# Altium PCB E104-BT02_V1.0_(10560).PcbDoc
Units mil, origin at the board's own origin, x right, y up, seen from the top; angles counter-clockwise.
Board outline 2052.36 x 953 mil, 2 copper layers (Top Layer, Bottom Layer); 31 components, 29 nets, 97 pads, 122 vias.
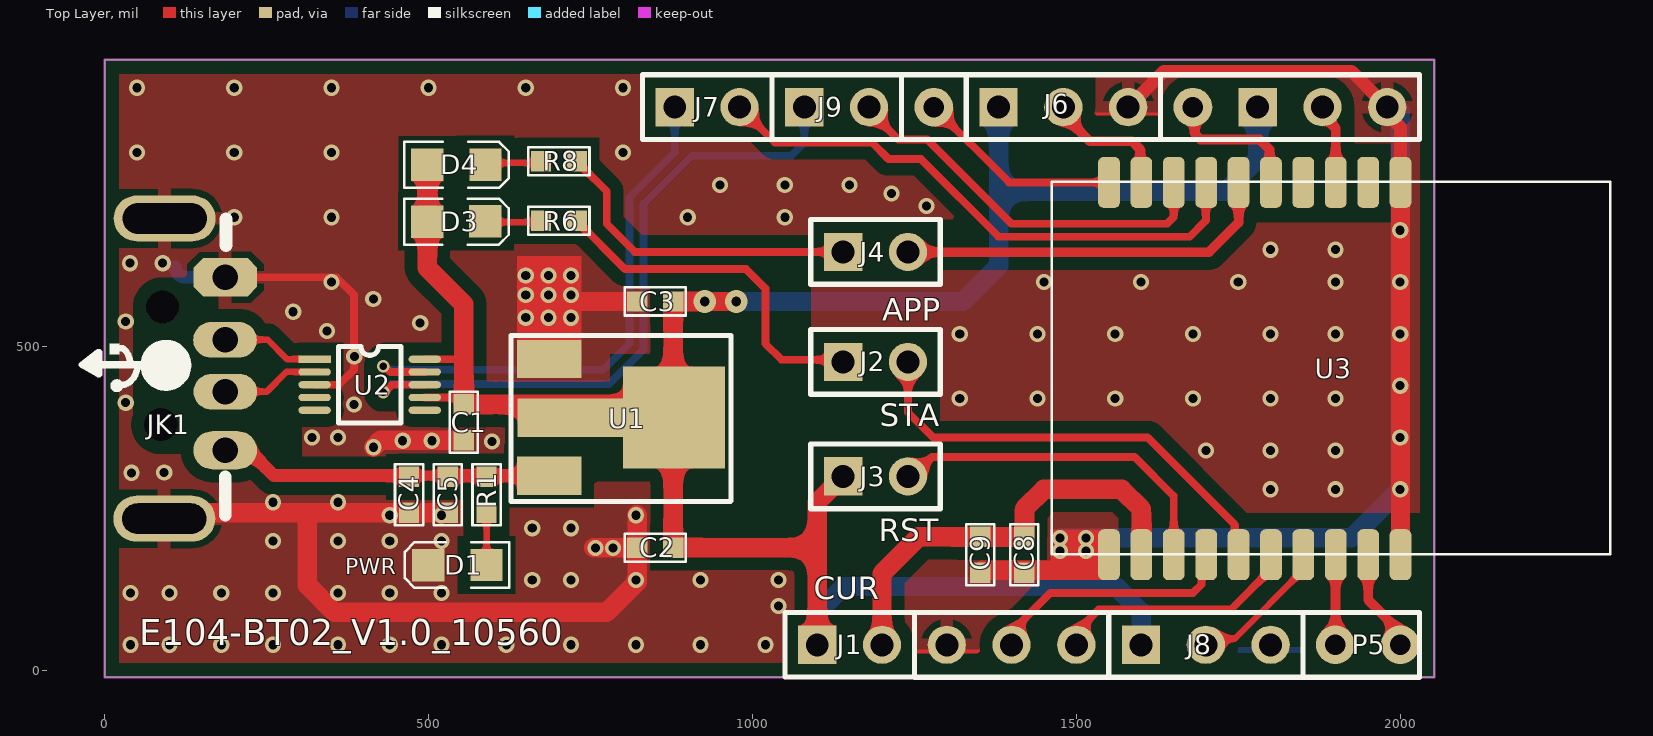
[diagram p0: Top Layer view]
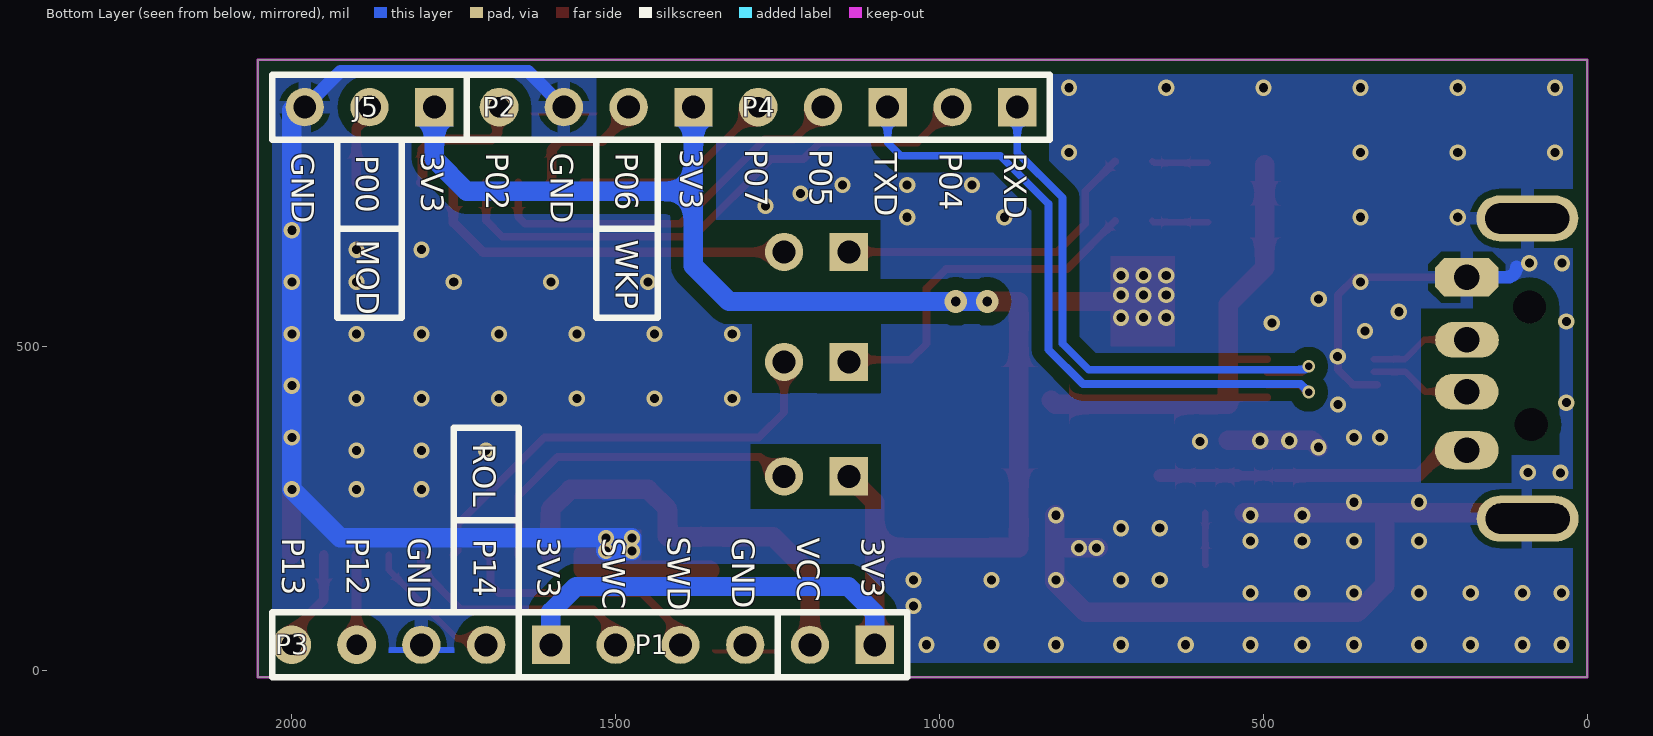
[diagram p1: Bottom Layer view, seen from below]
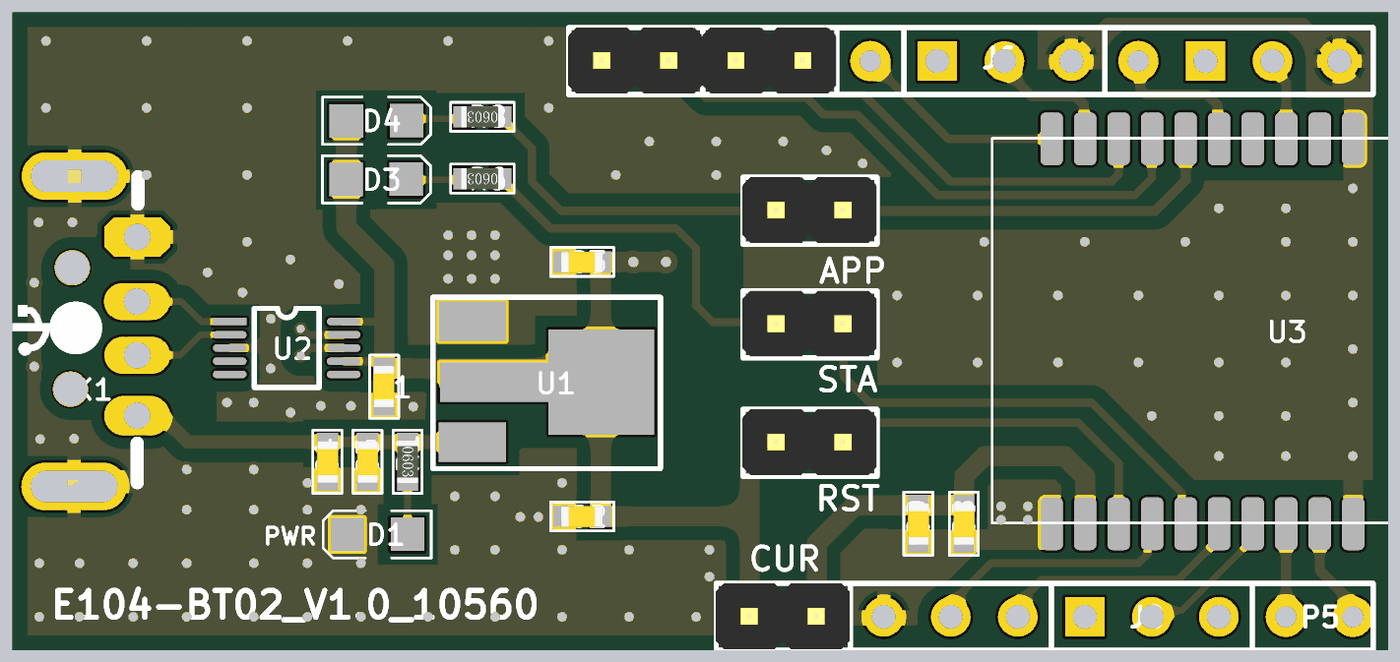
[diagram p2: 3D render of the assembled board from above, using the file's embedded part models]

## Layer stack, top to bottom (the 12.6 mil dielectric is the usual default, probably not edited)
Top Solder: solder mask 0.4, Solder Resist, Dk 3.5
Top Layer: signal copper 1.4
Dielectric1: dielectric 12.6, FR-4, Dk 4.8
Bottom Layer: signal copper 1.4
Bottom Solder: solder mask 0.4, Solder Resist, Dk 3.5

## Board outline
0,-10 2052.36,-10 2052.36,943 0,943

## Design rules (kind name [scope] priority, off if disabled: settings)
Clearance Clearance_1 [InPolygon] p1: gap=20 ignorepadtopadclearanceinfootprint=TRUE
Clearance [All] p2: gap=3 ignorepadtopadclearanceinfootprint=TRUE
ComponentClearance [All] p1 off: gap=10 collisioncheckmode=3 verticalgap=10 showdistances=FALSE
MinimumSolderMaskSliver [All] p1: minsoldermaskwidth=1
PolygonConnect PolygonConnect_4 [All vs IsNamedPolygon('Top Layer-No Net')] p1: thpad.connectstyle=Relief thpad.reliefconductorwidth=20 thpad.reliefentries=4 thpad.polygonreliefangle="90 Angle" thpad.airgapwidth=10 smdpad.connectstyle=Direct smdpad.reliefconductorwidth=10 smdpad.reliefentries=4 smdpad.polygonreliefangle="90 Angle" smdpad.airgapwidth=10 via.connectstyle=Direct via.reliefconductorwidth=10 via.reliefentries=4 via.polygonreliefangle="90 Angle" via.airgapwidth=10
PolygonConnect PolygonConnect_3 [All vs IsNamedPolygon('Top Layer-No Net')] p2: thpad.connectstyle=Relief thpad.reliefconductorwidth=20 thpad.reliefentries=4 thpad.polygonreliefangle="90 Angle" thpad.airgapwidth=10 smdpad.connectstyle=Direct smdpad.reliefconductorwidth=10 smdpad.reliefentries=4 smdpad.polygonreliefangle="90 Angle" smdpad.airgapwidth=10 via.connectstyle=Direct via.reliefconductorwidth=10 via.reliefentries=4 via.polygonreliefangle="90 Angle" via.airgapwidth=10
PolygonConnect PolygonConnect_2 [All vs IsNamedPolygon('Top Layer-No Net')] p3: thpad.connectstyle=Relief thpad.reliefconductorwidth=10 thpad.reliefentries=4 thpad.polygonreliefangle="90 Angle" thpad.airgapwidth=10 smdpad.connectstyle=Direct smdpad.reliefconductorwidth=10 smdpad.reliefentries=4 smdpad.polygonreliefangle="90 Angle" smdpad.airgapwidth=10 via.connectstyle=Direct via.reliefconductorwidth=10 via.reliefentries=4 via.polygonreliefangle="90 Angle" via.airgapwidth=10
PolygonConnect PolygonConnect_1 [All vs IsNamedPolygon('Top Layer-No Net')] p4: thpad.connectstyle=Relief thpad.reliefconductorwidth=10 thpad.reliefentries=4 thpad.polygonreliefangle="90 Angle" thpad.airgapwidth=10 smdpad.connectstyle=Direct smdpad.reliefconductorwidth=10 smdpad.reliefentries=4 smdpad.polygonreliefangle="90 Angle" smdpad.airgapwidth=10 via.connectstyle=Direct via.reliefconductorwidth=10 via.reliefentries=4 via.polygonreliefangle="90 Angle" via.airgapwidth=10
PolygonConnect [All] p5: connectstyle=Direct reliefconductorwidth=10 reliefentries=4 polygonreliefangle="90 Angle" airgapwidth=10
RoutingVias [All] p1: holewidth=28 width=50 viastyle="Through Hole" minholewidth=28 minwidth=50 maxholewidth=28 maxwidth=50
SilkToSilkClearance [All] p1: silktosilkclearance=1
SilkToSolderMaskClearance SilkscreenOverComponentPads [IsPad] p1: minsilkscreentomaskgap=1 clearancetoexposedcopper=TRUE
SolderMaskExpansion [All] p1: expansion=4 istentingtop=FALSE
Width [All] p1: maxlimit=50 minlimit=10 preferedwidth=10
26 further rules are at their usual default settings.

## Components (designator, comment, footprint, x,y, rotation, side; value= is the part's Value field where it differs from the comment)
C1 "Cap" E-CAP-0603 554.54,383.52 r90 top value=100nF
C2 "10uF" E-CAP-0603 850,190 r180 top
C3 "0u1F" E-CAP-0603 850,570 r180 top
C4 "10uF" E-CAP-0603 469.83,271.6 r270 top
C5 "0u1F" E-CAP-0603 529.66,271.6 r270 top
C8 "0.1uF" E-CAP-0603 1419.48,179 r270 top value=0.01uF
C9 "1uF" E-CAP-0603 1351.48,179 r270 top value=0.01uF
D1 "LED_RED" LED0805 544.48,163 r180 top
D3 "LED_GREEN" LED0805 542.67,693.49 r0 top
D4 "LED_RED" LED0805 542.96,781.01 r0 top
J1 "CUR" E-2P-2.54-1 1100,40 r0 top
J2 "J_STATE" E-2P-2.54-1 1140,476.74 r0 top
J3 "J_RESET" E-2P-2.54-1 1140,300 r0 top
J4 "J_APP" E-2P-2.54-1 1140,646.55 r0 top
J5 "J_MOD" E-3P-2.54-1 1880,870 r0 bottom
J6 "J_WK" E-3P-2.54-1 1480,870 r0 top
J7 "J_TX" E-2P-2.54-1 880,870 r0 top
J8 "J_ROLE" HDR1X3 1600,40 r0 top
J9 "J_RX" E-2P-2.54-1 1080,870 r0 top
JK1 "USB-A" USB-AG-DIP 136.36,466.4 r0 top
P1 "DBG" E-4P-2.54-1 1450,40 r180 bottom
P2 "P02" E-1×1P-1 1680,870 r180 bottom
P3 "P13" E-1×1P-1 2000,40 r0 bottom
P4 "P07" E-1×1P-1 1280,870 r0 bottom
P5 "P12" E-1×1P-1 1900,40 r0 top
R1 "1K" E-RES-0603 589.48,271.6 r270 top
R6 "1K" E-RES-0603 701.15,694.45 r180 top value=4K7
R8 "1K" E-RES-0603 701.15,786.74 r180 top value=4K7
U1 "AMS1117-3.3" SOT-223 782.36,391.13 r270 top
U2 "CH340X" MSOP10 324.13,480.86 r270 top
U3 "E104-BT02_V1.1" E104-BT02_V1.1 1775.48,466.4 r270 top locked

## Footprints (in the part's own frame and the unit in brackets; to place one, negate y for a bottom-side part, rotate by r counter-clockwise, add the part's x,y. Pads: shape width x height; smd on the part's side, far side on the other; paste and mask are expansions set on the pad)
E104-BT02_V1.1 [mm]
  rrect50% 2x0.85 smd: 1(-7.3,5.715) 2(-7.3,4.445) 3(-7.3,3.175) 4(-7.3,1.905) 5(-7.3,0.635) 6(-7.3,-0.635) 7(-7.3,-1.905) 8(-7.3,-3.175) 9(-7.3,-4.445) 10(-7.3,-5.715) 11(7.3,-5.715) 12(7.3,-4.445) 13(7.3,-3.175) 14(7.3,-1.905) 15(7.3,-0.635) 16(7.3,0.635) 17(7.3,1.905) 18(7.3,3.175) 19(7.3,4.445) 20(7.3,5.715)
  silkscreen extent -7.33,-7.96 7.27,13.94
E-1×1P-1 [mm]
  round 1.52 hole 0.8: 1(0,0)
E-2P-2.54-1 [mm] "Connector; Header;2pins"
  rect 1.5x1.5 hole 0.9: 1(0,0)
  round 1.5 hole 0.9: 2(2.54,0)
  silkscreen extent -1.27,-1.27 3.81,1.27, body extent -1.29,-1.22 3.79,1.27, height 8.54
E-3P-2.54-1 [mm] "Connector; Header; 3 pins"
  rect 1.5x1.5 hole 0.9: 1(-2.54,0)
  round 1.5 hole 0.9: 2(0,0) 3(2.54,0)
  silkscreen extent -3.81,-1.27 3.81,1.27
E-4P-2.54-1 [mm] "Connector; Header; 4pins"
  rect 1.5x1.5 hole 0.9: 1(-3.81,0)
  round 1.5 hole 0.9: 2(-1.27,0) 3(1.27,0) 4(3.81,0)
  silkscreen extent -5.08,-1.27 5.08,1.27
E-CAP-0603 [mm]
  rect 0.8x0.8 smd: 1(-0.7,0) 2(0.7,0)
  silkscreen extent -1.2,-0.55 1.2,0.55, body extent -0.79,-0.39 0.81,0.41, height 0.92
E-RES-0603 [mm]
  rect 0.8x0.8 smd: 1(-0.7,0) 2(0.7,0)
  silkscreen extent -1.2,-0.55 1.2,0.55, body extent -0.8,-0.4 0.8,0.4, height 0.45
HDR1X3 [mm] "Connector; Header; 3 Position"
  rect 1.5x1.5 hole 0.9: 1(0,0)
  round 1.5 hole 0.9: 2(2.54,0) 3(5.08,0)
  silkscreen extent -1.27,-1.27 6.35,1.27
LED0805 [mil]
  rect 50x50 smd: A(-44.9,-0.18) K(44.9,0.18)
  silkscreen extent -80,-36 81,35
MSOP10 [mil]
  rect 11x50 smd: 1(0,0)
  oval 11x50 smd: 2(19.68,0) 3(39.37,0) 4(59.06,0) 5(78.74,0) 6(78.74,170) 7(59.06,170) 8(39.37,170) 9(19.68,170) 10(0,170)
  silkscreen extent -20,37 98,133
SOT-223 [mm]
  rect 1.5x2.54 smd: 1(-2.29,-2.444) 3(2.29,-2.444)
  rect 4x4 smd: 2(0.013,2.444)
  rect 1.5x5.04 smd: 2(0.013,-1.156)
  silkscreen extent -3.21,-3.93 3.3,4.69
USB-AG-DIP [mm]
  oval 2.5x1.5 hole 1: 1(1.26,-3.202)
  oval 2.5x1.4 hole 1: 2(1.266,-0.909) 3(1.254,1.129)
  oct 2.5x1.5 hole 1: 4(1.266,3.581)
  oval 4x1.8 hole 1.2 slot 3.3 at 0 deg: 5(-1.127,-5.886) 6(-1.113,5.886)
  round 1.27 hole 1.3: 7(-1.198,2.41) 8(-1.266,-2.194)
  silkscreen extent -4.36,-5.74 1.29,5.87

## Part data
C1: "Capacitor"
C2 C3 C4 C5: library part cap0603, "0603"
C8 C9: library part Cap, "0603"
D1 D3 D4: library part LED, "0805"
J1 J2 J3 J4 J7 J9: library part JMP2, "HDR1X2"
J5 J6 J8: library part JMP3, "HDR1X3"
JK1: "USB-AG-DIP"
P1: library part "Header 4H", "HDR1X4"
P2 P3 P4 P5: library part "Header 1H", "HDR1X1"
R1: library part res0603, "0603"
R6 R8: library part Res2, "0603"
U1: "SOT-223"
U2: "USB to TTL Serial / UART"
U3: library part E104-BT02

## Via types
v1: diameter 25, hole 14, Top Layer to Bottom Layer, tented both sides, 118 vias
v2: diameter 20, hole 12, Top Layer to Bottom Layer, tented both sides, 2 vias
v3: diameter 35, hole 15, Top Layer to Bottom Layer, tented both sides, 2 vias

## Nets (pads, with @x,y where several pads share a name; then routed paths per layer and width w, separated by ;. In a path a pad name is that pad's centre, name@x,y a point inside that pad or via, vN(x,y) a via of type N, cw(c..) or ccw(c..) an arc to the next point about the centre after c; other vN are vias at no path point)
APP: J4.1 R8.1 | length 498.7
  Top Layer w12: R8.1@728.71,786.32 729.13,786.32 738.46,776.99 738.46,776.57 775,740.03 775,690 818.45,646.55 J4.1
DN: JK1.2 U2.2 | length 122.1
  Top Layer w10: JK1.2@220.48,431 250.48,431 280.79,461.31 U2.2@330,461.31
DP: JK1.3 U2.1 | length 123.9
  Top Layer w10: JK1.3@218.48,511 251.48,511 281.48,481 U2.1@330,481
GND: C1.1 C2.2 C3.2 C4.2 C5.2 C8.2 C9.2 D1.K J5.3 J6.3 J8.3 JK1.4 JK1.5 JK1.6 P1.4 U1.1 U2.3 U3.1 U3.11 U3.20 | length 5028.7
  Top Layer w12: JK1.4 357.62,607.38 385,580 385,465 361.49,441.49 U2.3
  Top Layer w20: J6.3 1635,925 1925,925 J5.3 1980,859.43 2000.48,838.95 2000.48,764.52 U3.1
  Top Layer w30: JK1.5 146.35,234.65 155.73,244.04 312.78,244.04 ; v1(415,345) 425.96,355.96 C1.1 ; C5.2 C4.2 312.78,244.04 ; 705,565 710,570 C3.2 ; v1@755,190 C2.2 ; v1(820,140) 820,135.46 774.54,90 355,90 312.78,132.22 312.78,244.04 ; v1@821.63,240.78 822.44,239.97 C2.2 ; v1@822.44,137.56 C2.2 ; C9.2@1355,155 1548.75,155 1550.48,156.73 U3.11 ; U3.1@2000,765 U3.1@2000.48,764.52 ; U3.20 U3.1
  Bottom Layer w20: 109,623 ccw(c124.62,623) 124.62,607.38 JK1.4 ; J6.3 1635,925 1925,925 J5.3
  Bottom Layer w30: v1(1515,185) v1(1475,185) v1(1475,205) v1(1515,205) 1925,205 v1(2000,280) v1(2000,360) v1(2000,440) v1(2000,520) v1(2000,600) v1(2000,680) J5.3@2000,865
  other v1: 40,40 100,40 180,40 260,40 360,40 440,40 520,40 620,40 720,40 820,40 920,40 1020,40 1040,100 40,120 100,120 180,120 260,120 360,120 440,120 520,120 660,140 720,140 920,140 1040,140 757.65,189.2 784.54,189.2 260,200 360,200 440,200 520,200 660,220 720,220 440,240 520,240 820,240 260,260 360,260 1800,280 1900,280 41.22,305.49 91.83,306.07 1700,340 1800,340 1900,340 598,354 460,355 505,355 320,360 360,360 385.06,410.83 32.4,413.76 1320,420 1440,420 1560,420 1680,420 1800,420 1900,420 385.35,485.2 1320,520 1440,520 1560,520 1680,520 1800,520 1900,520 343.22,524.24 487.02,537 32.4,539.09 650,545 685,545 720,545 290.95,554.11 414.7,573.7 650,580 685,580 720,580 350,600 1450,600 1600,600 1750,600 1900,600 650,610 685,610 720,610 38.87,629.12 89.47,629.12 1800,650 1900,650 200,700 350,700 900,700 1050,700 1268.51,717.26 1214.54,736.69 950,750 1050,750 1150,750 50,800 200,800 350,800 800,800 50,900 200,900 350,900 500,900 650,900 800,900
NC_VPP: U3.2
NetD1_A: D1.A R1.2 | length 80.9
  Top Layer w10: D1.A 589.48,163.28 R1.2
NetD3_K: D3.K R6.2 | length 87.3
  Top Layer w10: D3.K@585.05,692.63 669.8,692.63 R6.2@671.62,694.45
NetD4_K: D4.K R8.2 | length 86.6
  Top Layer w10: D4.K@586.15,783.92 668.8,783.92 R8.2@671.62,786.74
P00: J5.2 U3.3 | length 124.7
  Top Layer w15: J5.2 1880,858.08 1900.48,837.6 U3.3
P01: U3.4
P02: P2.1 U3.5 | length 219.5
  Top Layer w15: P2.1 1682.95,867.05 1682.95,828.81 1691.73,820.03 1782.86,820.03 1798.27,804.61 1798.27,756.01 U3.5
P03: J4.2 U3.6 | length 591.7
  Top Layer w15: J4.2 1240.35,646.2 1705,646.2 1750.58,691.78 1750.58,753.7 U3.6
P04: J7.2 U3.7 | length 872.2
  Top Layer w12: J7.2 1035,815 1185,815 1210,790 1260,790 1380,670 1675,670 1700,695 1700,753.32 U3.7
P05: J9.2 U3.8 | length 605.6
  Top Layer w12: J9.2 1180,865 1225,820 1270,820 1400,690 1640,690 1650.48,700.48 U3.8
P06: J6.2 U3.9 | length 204.5
  Top Layer w15: J6.2 1480,858.14 1520.6,817.55 1586.15,817.55 1598.68,805.02 1598.68,755.61 U3.9
P07: P4.1 U3.10 | length 318.6
  Top Layer w12: P4.1 1396.2,753.8 U3.10
P11: J2.2 U3.15 | length 703
  Top Layer w12: J2.2 1240,399.07 1279.07,360 1610,360 1744.41,225.59 1744.41,185.07 U3.15
P12: P5.1 U3.18 | length 139.2
  Top Layer w15: P5.1 1900.24,40.24 1900.24,178.76 U3.18
P13: P3.1 U3.19 | length 139.5
  Top Layer w15: U3.19 1950.48,109.52 P3.1@2000,60
P14: J8.2 U3.17 | length 221.8
  Top Layer w10: J8.2 1709.39,49.39 1744.39,49.39 1850.48,155.48 U3.17
RESET_H: J3.2 U3.13 | length 538.5
  Top Layer w12: J3.2 1247.21,300 1277.21,330 1590,330 1650.48,269.52 U3.13
STATE: J2.1 R6.1 | length 551.3
  Top Layer w12: R6.1 803.16,620 990,620 1020,590 1020,505 1045,480 1136.74,480 J2.1
SWC: P1.2 U3.16 | length 363
  Top Layer w12: P1.2@1500,60 1535,95 1739.12,95 1800.48,156.36 U3.16
SWD: P1.3 U3.14 | length 372.3
  Top Layer w12: P1.3@1400,60 1460,120 1680,120 1693.41,133.41 1693.41,171.93 U3.14
TTL_RXD: J7.1 U2.9 | length 860.8
  Top Layer w12: v2(430,470) 432.16,470 440.99,461.17 U2.9
  Bottom Layer w12: v2(430,470) 435.5,464.5 769.5,464.5 810,505 810,730 880,800 J7.1
TTL_TXD: J9.1 U2.8 | length 1065.2
  Top Layer w12: v2(430,430) 432.16,430 443.65,441.49 U2.8
  Bottom Layer w12: v2(430,430) 442.5,442.5 778.61,442.5 832,495.89 832,720.89 906.11,795 1060,795 1080,815 J9.1
V3.3: C1.2 C2.1 C3.1 D3.A D4.A J1.1 J3.1 J5.1 J6.1 J8.1 P1.1 U1.2 U2.7 U2.10 | length 3568.6
  Top Layer w12: U2.7 543.81,421.8 C1.2 ; U2.10 547.12,480.86 554.54,488.27
  Top Layer w30: D4.A 498.06,621.94 554.54,565.46 554.54,488.27 C1.2 821.25,411.08 U1.2@827.37,417.19 ; v3(975,570) v3(926.28,570) C3.1 C2.1 1100,190 ; J1.1@1100,60 1100,190 ; J3.1 1100,260 1100,190
  Bottom Layer w30: v3(926.28,570) v3(975,570) 1325,570 1380,625 1380,740 ; J1.1@1100,60 1100,89 1141,130 1561,130 1600,91 J8.1@1600,60 ; J6.1 1380,740 ; J5.1 1780,790 1730,740 1380,740
VBUS: C4.1 C5.1 JK1.1 R1.1 U1.3 | length 609.4
  Top Layer w15: C4.1@480.01,301.13 539.83,301.13 599.66,301.13 U1.3@659.48,301.13
  Top Layer w20: JK1.1 222.27,340.34 261.48,301.13 C4.1@480.01,301.13 ; C5.1@539.83,301.13 599.66,301.13 U1.3@659.48,301.13
VCC: C8.1 C9.1 J1.2 U3.12 | length 652.6
  Top Layer w30: J1.2@1200,60 1200,150 1256.56,206.56 C9.1 C8.1 1420.23,207.31 1420.23,250.23 1450,280 1570,280 1600.48,249.52 U3.12
pads on no net: JK1.7 JK1.8 U2.4 U2.5 U2.6

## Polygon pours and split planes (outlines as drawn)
GND on Top Layer "Top Layer-No Net" (solid, remove dead copper, pour order 1000): 0,933 2042.36,933 2042.36,0 0,0
GND on Bottom Layer "Top Layer-No Net" (solid, remove dead copper, pour order 1001): 0,933 2042.36,933 2042.36,0 0,0

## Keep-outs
Keep-Out Layer:
  the board outline again, w3.94

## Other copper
Top Layer:
  rectangle net GND: 1459.82,152.95 1549.82,217.95
  rectangle net GND: 636.12,500.51 736.12,640.51
  pour cut-out: 89.18,607.25 ccw(c89.18,561.27) 43.2,561.27 43.2,382.68 cw(c40.53,382.68) 40.53,380.02 ccw(c86.51,380.02) 86.51,334.03 143,334.03 143,606 cw(c144,606) 144,607
  pour cut-out: 474.63,506.86 436.6,506.86 ccw(c436.6,470) 399.74,470 399.74,430 ccw(c430,430) 430,399.74 475,399.74
  region net GND: 1528.8,861.23 1528.8,860.77 ccw(c1532.1,860.77) 1532.1,857.47 1627.04,857.47 ccw(c1627.04,861.23) 1630.8,861.23
  region net GND: 1248.9,31.98 1248.9,31.4 ccw(c1253.05,31.4) 1253.05,27.25 1346.37,27.25 ccw(c1346.37,31.98) 1351.1,31.98
  pour cut-out: -29.86,280.48 81.98,280.48 81.98,189 -25,189
  pour cut-out: 82.54,743.98 82.54,652.33 -11,652.33 -11,744 -14,744
  pour cut-out: 304.63,376.12 304.63,322 221,322 221,429 286,429
  pour cut-out: 637.84,658.7 637.84,667.14 631.94,667.14 631.94,658.62
  pour cut-out: 779.84,291.88 779.84,341.09 756.13,341.09 756.13,292 756,292
  pour cut-out: 830.47,820.47 830.47,924 1017,924 1017,820
  pour cut-out: 1090.47,620.33 1090.47,506.22 1020,506.22 1020,627 1015,627
  pour cut-out: 1289,696.65 1289,669 1343,669 1343,697
  pour cut-out: 1090.47,696.08 1090.47,596.6 1289,596.6 1289,696.65
  pour cut-out: 1090.47,526.27 1289.95,526.27 1289.95,385 1091.24,385
  pour cut-out: 1529.95,870 1529.95,923 1480,923
  pour cut-out: 1645.14,857.47 1667,809 1513,809 1521.63,857.47
  pour cut-out: 1930.01,808.97 1930.01,870 1910,870 1910,868
  pour cut-out: 1986.48,792.21 1986.48,814.25 1928.22,814.25
  pour cut-out: 1778.32,691.78 1986.48,691.78 1986.48,792.21
  pour cut-out: 1763,244 2042,244 2042,61
  pour cut-out: 1234,-4 1367,-4 1367,26.98 1234.91,26.98
  pour cut-out: 1809,95 1809,5 1876,5 1876,141
  pour cut-out: 176,568 176,548 130,548 130,582
Bottom Layer:
  pour cut-out: 830.47,820.47 853.78,820.47 853.78,778.44 830.54,778.44
  pour cut-out: 1106.22,820.47 1106.22,818.92 1344,818.92 1344,864 1106,864
  pour cut-out: 1829.53,820.47 1880,820.47 1880,870 1827,870
  pour cut-out: 1529.95,818 1629.65,818 1629.65,766 1529.95,766
  pour cut-out: 1529.95,870 1529.95,932 1476,932
  pour cut-out: 1629.65,870 1629.65,768 1746,768 1746,861
  pour cut-out: 1529.95,870 1529.95,766 1409,766 1409,855
  pour cut-out: 1900,90.35 2034,90.35 2034,-5 1900,-5
  pour cut-out: 1635.3,89.53 1700,89.53 1700,40 1635,40 1635,39
  pour cut-out: 85.54,280.98 85.54,189 11,189 11,281
  pour cut-out: 82.54,743.98 82.54,652 8,652 8,744
  pour cut-out: 126.98,597.38 109.52,597.38 109.52,591.26 128.8,591.26
  pour cut-out: 43.2,561.27 43.2,333.33 120,333.33 120,561.1 120.35,561.1
  pour cut-out: 256,559 256,290 117,290 117,559 257,559
  pour cut-out: 176,568 176,548 130,548 130,582
  pour cut-out: 1090.43,349.46 1090.43,250 1291.41,250 1291.41,349.24
  pour cut-out: 1090,428 1090,541 1290,541 1290,428
  pour cut-out: 1091,696 1346,696 1346,597 1091,597
  pour cut-out: 1121,125 1121,8 1567,8 1567,124
  region net GND: 1749,34 1749,28 1850.53,28 1850.53,33.84 1849,36 1751,36
  pour cut-out: 1745,30 1745,10 1860,10 1860,30

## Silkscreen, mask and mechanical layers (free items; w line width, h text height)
Top Overlay:
  lines w8: 1224.97,820.03 1330,820.03 1330,920 1230,920 ; 1250,-10 2030,-10 2030,90 1250,90 ; 1630,820.03 2030,820.03 2030,920 1630,920
  text "APP" at 1200,540 h35
  text "STA" at 1196.52,377.74 h35
  text "RST" at 1195,200 h35
  text "PWR" at 371.59,148.58 h25
  text "CUR" at 1095,110 h35
  text "E104-BT02_V1.0_10560" at 53,39 h40
Bottom Overlay:
  lines w10: 1250,90 1050,90 1050,-10 2030,-10 2030,90 1650,90 1650,375 1750,375 1750,90 ; 1435,690 1435,682.5 1530,682.5 ; 1435,820 1435,545 1530,545 1530,820 ; 1650,232.5 1750,232.5 ; 1730,820.03 830,820.03 830,920 1730,920 ; 1830,682.51 1830,682.5 1930,682.5 ; 1830,820.03 1830,545 1930,545 1930,820
  text "P05" at 1200.49,804.8 h35 r90
  text "P07" at 1300,805 h35 r90
  text "3V3" at 1400,805 h35 r90
  text "RXD" at 900,800 h35 r90
  text "P04" at 1000,800 h35 r90
  text "TXD" at 1100,800 h35 r90
  text "P06" at 1500,800 h35 r90
  text "GND" at 1600,800 h35 r90
  text "P02" at 1700,800 h35 r90
  text "3V3" at 1800,800 h35 r90
  text "GND" at 2000,800 h35 r90
  text "P00" at 1900.48,795.7 h35 r90
  text "WKP" at 1500,665 h35 r90
  text "MOD" at 1900,665 h35 r90
  text "ROL" at 1720,350 h35 r90
  text "SWD" at 1419.85,206.93 h35 r90
  text "3V3" at 1120,205 h35 r90
  text "VCC" at 1220,205 h35 r90
  text "GND" at 1320,205 h35 r90
  text "SWC" at 1520,205 h35 r90
  text "3V3" at 1620,205 h35 r90
  text "GND" at 1820,205 h35 r90
  text "P12" at 1915,205 h35 r90
  text "P13" at 2015,205 h35 r90
  text "P14" at 1719,203 h35 r90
